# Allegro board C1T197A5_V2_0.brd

Outline 36.2 x 146 mm; copper layers: TOP, KEY, BOTTOM. Coordinates in mm from the lower left corner of the outline.
Outline path: circle c8.8,80.1 r1.2 ; circle c8.86,139.5 r0.85 ; circle c11.75,43.55 r1.2 ; circle c11.75,19.35 r1.2 ; rectangle 15.9,132.2 20.4,134.2 ; circle c18.1,128 r1.2 ; circle c24.45,43.55 r1.2 ; circle c24.45,19.35 r1.2 ; circle c27.4,80.1 r1.2 ; circle c34.26,139.5 r0.85 ; 0,144 0,4 arc(1.17,1.17) 4,0 32.2,0 arc(35.03,1.17) 36.2,4 36.2,144 arc(35.61,145.41) 34.2,146 26.2,146 arc(25.49,145.71) 25.2,145 25.2,143.8 arc(24.91,143.09) 24.2,142.8 12,142.8 arc(11.29,143.09) 11,143.8 11,145 arc(10.71,145.71) 10,146 2,146 arc(0.59,145.41) 0,144

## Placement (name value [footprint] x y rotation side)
BT2  3V_2xAAA  [BAT_2DIP]  18.1 4.11 0 bottom
C1  NC  [0402]  21.17 115.84 90 bottom
C2  NC  [0402]  23.94 115.83 90 bottom
C3  NC  [0402]  26.76 115.84 90 bottom
C4  220pF  [0402]  22.55 116.33 0 bottom
C5  0.1uF  [0402]  21.83 113.92 90 bottom
C6  2.2uF  [0402]  22.71 113.92 90 bottom
C7  1uF  [0402]  22.19 117.27 0 bottom
C8  NC  [0402]  29.55 115.84 270 bottom
C9  1uF  [0402]  14.74 122.87 270 bottom
C10  1uF  [0402]  11.29 118.98 270 bottom
C12  1uF  [0402]  11.12 111.75 90 bottom
C13  NC  [0402]  21.62 122.84 270 bottom
C14  NC  [0402]  15.79 123.38 90 bottom
C15  1uF  [0402]  10.22 111.75 90 bottom
C16  1uF  [0402]  10.11 115.83 0 bottom
C17  0.1uF  [0402]  10.11 116.68 0 bottom
C18  1uF  [0402]  10.11 117.53 0 bottom
C19  NC  [0402]  12.86 124.7 0 bottom
C20  NC  [0402]  12.7 129.33 270 bottom
C22  22nF  [0402]  7.65 128.53 180 bottom
C25  1uF  [0603C]  10.73 130.58 90 bottom
C26  10uF  [0603C]  12.52 71.93 0 bottom
C31  10uF  [0603C]  11.47 138.52 270 bottom
C33  0.1uF  [0603C]  15.42 130.26 0 bottom
CD2  220uF/10V  [CD2P0_4P0B1]  12.77 67.59 0 bottom
D1  Red_LED  [1206-LED]  17.04 133.22 90 bottom
D2  Red_LED  [1206-LED]  19.29 133.22 90 bottom
D3  LED  [LED_SMD_2P54MM_2PIN]  18.45 138.15 180 bottom
L1  0R  [0402]  25.34 116.33 0 bottom
L3  4.7uH  [0805L]  7.82 113.47 0 bottom
Q2  C1815  [SOT-23]  8.42 135.62 90 bottom
R1  1K  [0402]  21.73 130.86 180 bottom
R2  1K  [0402]  21.72 131.67 180 bottom
R3  NC  [0402]  14.15 125.86 90 bottom
R4  0R  [0402]  9.65 128.5 0 bottom
R6  0R  [0402]  28.15 116.35 0 bottom
R7  680  [0603R]  24.85 122.55 90 bottom
R10  1  [0402]  13.03 138.19 90 bottom
R11  NC  [0402]  7.87 131.17 180 bottom
R13  1K  [0402]  6.27 131.68 90 bottom
R48  0  [1206R]  7.6 110.21 315 bottom
R49  0  [1206R]  6.28 122.27 225 bottom
R50  0  [1206R]  6 117.75 135 bottom
SW1  SW2PIN  [KEY1]  13.45 73.6 180 top
SW2  SW2PIN  [KEY1]  30.8 133.5 180 top
SW3  SW2PIN  [KEY1]  5.4 133.5 180 top
SW4  SW2PIN  [KEY1]  22.75 73.6 180 top
SW5  SW2PIN  [KEY1]  4.15 73.6 180 top
SW8  SW2PIN  [KEY1]  18.1 62 180 top
SW9  SW2PIN  [KEY1]  32.05 122.1 180 top
SW10  SW2PIN  [KEY1]  4.15 122.1 0 top
SW11  SW2PIN  [KEY1]  30.6 62 180 top
SW12  SW2PIN  [KEY1]  5.6 62 180 top
SW15  SW2PIN  [KEY1]  18.1 49.6 180 top
SW16  SW2PIN  [KEY1]  31.6 98 180 top
SW17  SW2PIN  [KEY1]  13.45 122.1 0 top
SW18  SW2PIN  [KEY1]  30.8 49.6 270 top
SW19  SW2PIN  [KEY1]  5.4 49.6 90 top
SW22  SW2PIN  [KEY1]  18.1 37.5 180 top
SW23  SW2PIN  [KEY1]  18.1 98 270 top
SW24  SW2PIN  [KEY1]  22.75 122.1 0 top
SW25  SW2PIN  [KEY1]  30.8 37.5 270 top
SW26  SW2PIN  [KEY1]  5.4 37.5 90 top
SW29  SW2PIN  [KEY1]  18.1 25.4 180 top
SW30  SW2PIN  [KEY1]  18.1 84.5 270 top
SW31  SW2PIN  [KEY1]  18.1 111.5 0 top
SW32  SW2PIN  [KEY1]  30.8 25.4 180 top
SW33  SW2PIN  [KEY1]  32.05 73.6 180 top
SW34  SW2PIN  [KEY1]  18.1 13.3 180 top
SW35  SW2PIN  [KEY1]  30.8 13.3 270 top
SW36  SW2PIN  [KEY1]  4.6 98 180 top
SW37  SW2PIN  [KEY1]  5.4 25.4 180 top
SW38  SW2PIN  [KEY1]  5.4 13.3 90 top
TP2  SWS  [TP100]  12.57 100.75 180 bottom
TP3  VDD  [TP100]  5.31 8.31 180 bottom
TP4  GND  [TP100]  31.03 8.51 180 bottom
TP5  TX  [TP100]  10.87 102.89 180 bottom
TP8  RX  [TP100]  12.8 102.85 180 bottom
U1  TLSR8278F1KET48  [QFN_7X7_48PIN_0P5_4P20X4P20]  16.12 115.08 90 bottom
U4  -  [SPU0410LR5H-QB]  13.29 133.86 0 bottom
Y1  24MHz-12pF-+/-20ppm  [OSCCC250X320X110]  18.75 122.91 270 bottom
Y2  32.768KHz - 9pf - +/-20ppm  [OSC_2X6_SMT]  8.8 126.85 0 bottom

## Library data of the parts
BT2 = BATTERY_2xAAA_3V
C1 = C1608_NC_8
C2 = C1608_NC_2
C3 = C1608_NC_6
C4 = C1608_NC_5
C5-C7 C9 C10 = C1005X5R1C104K
C8 = C1608_NC_7
C12 C15-C18 C25 = C1005X5R1C105K
C13 C14 = C1005_NC
C19 = C1608_NC_3
C20 = C1608_NC_4
C22 = C1005C0G1H223J
C26 = C1608X5R0J106M_0
C31 = C1608X5R1A226M
C33 = C1608X5R0J106M
CD2 = CD_220uF_16V
D1 D2 = 0603D_Red: Tolerance: RichardLC; User Part Number: pn
D3 = Led_Th_3mm_1: Tolerance: RichardLC; User Part Number: partnum
L1 = MLK1608_0
L3 = IND_0
Q2 = NPN_C1815
R1 R2 R4 R6 R7 = RS0402K472JT
R3 = RS0603K102JT_0
R10 = RS0805K1R0JT
R11 = RS0402_NC
R13 = RS0402K101JT
R48-R50 = RS1206_NC
SW1-SW5 SW8-SW12 SW15-SW19 SW22-SW26 SW29-SW38 = SW2PIN_0
TP2-TP5 TP8 = TestPad100
U1 = TLSR8278F1KET48_0
U4 = MULPS4CX-RM5_1
Y1 = CRYSTAL4/SM_0: Tolerance: RichardLC
Y2 = OSC_2x6_2pin_16Mhz

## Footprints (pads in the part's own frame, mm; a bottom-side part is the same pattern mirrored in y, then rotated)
0402
  rect 0.5x0.5 smd: 1(-0.5,0) 2(0.5,0)
0603C
  rect 0.8x0.8 smd: 1(-0.8,0) 2(0.8,0)
0603R
  rect 0.8x0.8 smd: 1(-0.8,0) 2(0.8,0)
0805L
  rect 1x1.2 smd: 1(-1,0) 2(1,0)
1206-LED
  rect 0.85x1.7 smd: A(-1.525,0) C(1.525,0)
1206R
  rect 0.8x1.8 smd: 1(-1.55,0) 2(1.55,0)
BAT_2DIP
  oval 0x0.8 hole 0.7x3.5: 1(-12.8,0) 2(12.8,0)
CD2P0_4P0B1
  round 0.7 hole 0.7 unplated: (-1,0) (1,0)
KEY1
  rect 0.5x0.5 smd: 1(0,0) 2(0,2.5)
LED_SMD_2P54MM_2PIN
  oval 2x4 smd: A(1.27,0) C(-1.27,0)
OSC_2X6_SMT
  oval 1.4x1.1 smd: 1(4,0.76) 2(4,-0.76)
OSCCC250X320X110
  rect 1.3x1.4 smd: 1(-0.965,1.265) 2(-0.965,-1.265) 3(0.965,-1.265) 4(0.965,1.265)
QFN_7X7_48PIN_0P5_4P20X4P20
  oval 0.6x0.26 smd: 1(-3.35,2.75) 2(-3.35,2.25) 3(-3.35,1.75) 4(-3.35,1.25) 5(-3.35,0.75) 6(-3.35,0.25) 7(-3.35,-0.25) 8(-3.35,-0.75) 9(-3.35,-1.25) 10(-3.35,-1.75) 11(-3.35,-2.25) 12(-3.35,-2.75) 25(3.35,-2.75) 26(3.35,-2.25) 27(3.35,-1.75) 28(3.35,-1.25) 29(3.35,-0.75) 30(3.35,-0.25) 31(3.35,0.25) 32(3.35,0.75) 33(3.35,1.25) 34(3.35,1.75) 35(3.35,2.25) 36(3.35,2.75)
  oval 0.26x0.6 smd: 13(-2.75,-3.35) 14(-2.25,-3.35) 15(-1.75,-3.35) 16(-1.25,-3.35) 17(-0.75,-3.35) 18(-0.25,-3.35) 19(0.25,-3.35) 20(0.75,-3.35) 21(1.25,-3.35) 22(1.75,-3.35) 23(2.25,-3.35) 24(2.75,-3.35) 37(2.75,3.35) 38(2.25,3.35) 39(1.75,3.35) 40(1.25,3.35) 41(0.75,3.35) 42(0.25,3.35) 43(-0.25,3.35) 44(-0.75,3.35) 45(-1.25,3.35) 46(-1.75,3.35) 47(-2.25,3.35) 48(-2.75,3.35)
  rect 4.2x4.2 smd: 49(0,0)
SOT-23
  rect 0.75x1.2 smd: 1(-1.016,-1.092) 2(1.016,-1.092) 3(0,1.092)
SPU0410LR5H-QB
  round 0.85 hole 0.85 unplated: (0,0)
  round 0.723 smd: 1(-0.966,2.103) 4(0.966,2.103)
  round 0.562 smd: 2(-1.015,-0.634) 3(1.016,-0.634)
  round 0.612 smd: 5(0,2.103)
TP100
  round 1 smd: 1(0,0)

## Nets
1V4: C5.2 C6.2 C16.2 C17.2 U1.19(VDD1V2) U1.20(AVDD1V2#20) U1.41(AVDD1V2#41)
GND: BT2.2(-) C1.1 C2.1 C3.1 C5.1 C6.1 C7.2 C8.2 C9.1 C10.2 C12.1 C13.1 C14.1 C15.1 C16.1 C17.1 C18.1 C19.1 C20.1 C22.2 C26.2 C31.2 C33.2 D1.C(CATHODE) D2.C(CATHODE) Q2.2(E) R11.1 R48.1 R48.2 R49.1 R49.2 R50.1 R50.2 TP4.1(TP) U1.7(DM/A[5]) U1.8(DP(SWS)/A[6]) U1.14(DVSS) U1.22(SDMP0/P4/CMP_D/B[4]) U1.23(SDMN0/P5/CMP_DF/B[5]) U1.24(SDMP1/DI/SDA/URTS/B[6]) U1.28(SDA/P4N/URTS/MDEC/C[0]) U1.42(CYC2LNA/CMP_D/7816TRX/UTX/MDEC/) U1.43(CYC2PA/CMP_DF/UCTS/D[1]) U1.49(GND) U4.2(GND#2) U4.3(GND#3) U4.5(GND#5) Y1.2 Y1.4
TL_32KI_C3: C20.2 R3.2 U1.31(P1/URX/SCK/32KIN/C[3]) Y2.2
TL_32KO_C2: C19.2 R3.1 U1.30(P0/7816TRX/UTX/SDA/32KO/C[2]) Y2.1
TL_AMICBIAS: R7.1 U1.35(P2/UCTS/P0/C[4])
TL_AMICSP: C22.1 R4.1 U1.29(SCK/P1N/P0/AUDIO_IN/C[1])
TL_ANT: C1.2 C4.1 U1.40(ANT)
TL_B0: TP8.1(TP) U1.10(P3/URX/ATSEL1/MDEC/B[0])
TL_B1: TP5.1(TP) U1.11(P4/UTX/ATSEL2/B[1])
TL_COL0: SW1.1 SW2.1 SW3.1 SW4.1 SW5.1 U1.36(P3N/URX/ATSEL0/C[5])
TL_COL1: SW8.1 SW9.1 SW10.1 SW11.1 SW12.1 U1.2(DMIC_DI/P0N/URX/MDEC/A[0])
TL_COL2: SW15.1 SW16.1 SW17.1 SW18.1 SW19.1 U1.12(P5/UCTS/CYC2LNA/B[2])
TL_COL3: SW22.1 SW23.1 SW24.1 SW25.1 SW26.1 U1.6(CK/SCL/URTS/P2/A[4])
TL_COL4: SW29.1 SW30.1 SW31.1 SW32.1 SW37.1 U1.5(DI/SDA/UCTS/P1/A[3])
TL_COL5: SW33.1 SW34.1 SW35.1 SW36.1 SW38.1 U1.45(P1N/I2SSDI/7816TRX/UTX/D[3])
TL_IROUT: R11.2 R13.1 U1.13(P0N/URTS/CYC2PA/B[3])
TL_LED1: R1.1 U1.37(CYC2LNA/ATSEL1/P4N/C[6])
TL_LED2: R2.1 U1.38(CYC2PA/ATSEL2/P5N/C[7])
TL_ROW0: SW1.2 SW8.2 SW15.2 SW22.2 SW29.2 SW34.2 U1.47(P0/CMP_D/P0N/D[5])
TL_ROW1: SW2.2 SW9.2 SW16.2 SW23.2 SW30.2 SW33.2 U1.44(CN/I2SLR/P3/D[2])
TL_ROW2: SW3.2 SW10.2 SW17.2 SW24.2 SW31.2 SW36.2 U1.46(SWM/I2SSDO/P2N/D[4])
TL_ROW3: SW4.2 SW11.2 SW18.2 SW25.2 SW32.2 SW35.2 U1.48(CN/URX/ATSEL0/D[6])
TL_ROW4: SW5.2 SW12.2 SW19.2 SW26.2 SW37.2 SW38.2 U1.1(CK/SCL/I2SBCK/7816TRX/UTX/D[7])
TL_RST: C7.1 U1.39(RESETB)
TL_SWS: TP2.1(TP) U1.9(SWS/URTS/A[7])
TL_VDD: BT2.1(+) C10.1 C15.2 C26.1 C31.1 R10.2 TP3.1(TP) U1.16(VDD_IO) U1.27(VDD3)
TL_XC1: C13.2 U1.34(XC1) Y1.3
TL_XC2: C14.2 U1.33(XC2) Y1.1
N21000893: D2.A(ANODE) R2.2
N21007782: D1.A(ANODE) R1.2
N21115397: C8.1 R6.2
N21115407: C2.2 C4.2 L1.1
N21115415: C3.2 L1.2 R6.1
N21116055: C12.2 U1.15(VDD1V)
N21116211: L3.2 U1.17(VDCDC_SW)
N21116214: L3.1 U1.18(VDCDC)
N21116508: C18.2 U1.21(VDD_F)
N21117063: C9.2 U1.32(VMID)
N21140224: C25.2 U4.1(OUTPUT)
N21140411: C33.1 R7.2 U4.4(VDD)
N21149600: C25.1 R4.2
N21152572: D3.A(ANODE) R10.1
N21152638: Q2.1(B) R13.2
N21152650: D3.C(CATHODE) Q2.3(C)

Pads without a net: U1 3 4 25 26

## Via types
v1: diameter 1.5, hole 0.7, TOP to BOTTOM, 25 vias
v2: diameter 1.5, hole 0.001, TOP to BOTTOM, 27 vias

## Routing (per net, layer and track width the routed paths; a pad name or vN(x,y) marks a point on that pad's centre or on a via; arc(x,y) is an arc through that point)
1V4: length 19.3
  BOTTOM w0.3: C5.2 21.73,114.52 21.56,114.52 21.55,114.53 20.98,114.53 20.78,114.74 20.57,114.94 20.57,115.13 19.87,115.83 U1.41 18.72,115.83 18.57,115.98 18.57,117.32 18.36,117.53 13.87,117.53 13.67,117.32 13.67,116.12 13.37,115.83 U1.20 11.86,115.83 11.01,116.68 C17.2 C16.2 11.11,115.33 U1.19
  BOTTOM w0.5: C5.2 21.84,114.42 C6.2
GND: length 428.2
  BOTTOM w0.2: C12.1 11.07,111.3 ; 22,113.1 21.73,113.1 20.97,113.87 ; U1.23 12.17,117.33 12,117.5 ; 12,112.1 11.15,111.25 ; U1.28 14.87,119.23 14.04,120.06 12.64,120.06 12.4,120.3 12.1,120.3 ; 30.9,10.01 31.03,9.88 ; U1.22 12.24,116.83 12,117.07 ; 20.8,114.08 21.04,114.08 21.19,113.93 21.13,113.87 20.97,113.87 ; 20.8,114.08 20.76,114.12 20.72,114.12 20.01,114.83 20.01,115.06 19.74,115.33 U1.42 16.37,115.33 U1.49 ; 20.8,114.08 20.8,114.04 20.97,113.87 ; 21.22,115.34 C1.1 21.07,115.34 ; 11.9,117.9 11.97,117.83 U1.24 ; 15.37,114.33 U1.8 15.37,108.78 ; 15.87,114.83 U1.7 15.87,109.41
  BOTTOM w0.3: 12.12,112.51 12.12,112.53 12.42,112.83 ; 23.92,122.55 25.72,122.55 25.81,122.64 ; 16.37,114.83 16.12,114.83 U1.49 ; 16.37,114.83 U1.49 ; 16.37,114.83 U1.43 20.01,114.83 ; 19.3,119.1 19.5,119.3 ; 19.4,119.1 22.84,119.1 23.24,119.5 23.8,119.5 ; 12.42,112.83 U1.14 13.87,112.83 U1.49 ; 12.42,112.83 12.03,112.83 12,112.8 12,112.39 11.87,112.27
  BOTTOM w0.4: 24,119.3 19.6,119.3 19.4,119.1 19.3,119.1 ; C14.1 15.79,121.56 16.95,120.4 16.95,120.43 17.49,120.97 Y1.4
  BOTTOM w0.5: 21.19,113.93 21.7,113.42 C5.1 ; 21.6,124.6 21.2,125 16.2,125 16.1,124.9 15.4,124.9 14.74,124.24 C9.1 14.81,123.37 15.11,123.07 15.18,123.07 15.37,122.88 C14.1 16.73,121.94 Y1.4 ; 21.6,124.6 22.35,123.85 22.35,121.55 ; 21.6,124.6 21.6,123.36 C13.1 ; C7.2 27.16,117.27 27.59,117.7 ; 10.4,118.51 10.2,118.71 10,118.51 ; 10.4,118.51 10.86,118.51 11.06,118.71 C10.2 ; 10.4,118.51 10,118.51 ; 23.83,122.64 23.49,122.3 23.1,122.3 22.35,121.55 ; 23.83,122.64 22.84,123.63 22.84,124.17 21.81,125.19 21.59,125.19 21.56,125.22 16.7,125.22 15.94,125.98 ; 23.83,122.64 23.92,122.55 ; 22.35,121.55 21.7,120.9 21.7,120.8 21.1,120.8 ; C12.1 11.45,111.25 12,111.8 12,112.39 ; 18.53,119.87 18.7,120.05 18.71,120.05 19.46,120.8 21.1,120.8 ; 11.49,124.7 11.01,124.7 11,124.71 ; 11.49,124.7 11,124.21 ; 11.49,124.7 C19.1 ; 15.8,130.01 15.47,130.34 15.47,130.85 15.4,130.91 15.4,131.08 ; C33.2 15.4,131.08 ; 15.4,131.08 15.4,132.51 ; 12,122.61 12,122.31 13.3,121.01 ; 21.7,121.4 21.1,120.8 ; 11.9,120.33 12.08,120.33 12.23,120.18 12.3,120.18 ; 8.37,131.95 8.2,132.12 8.2,133.86 8.38,134.04 8.38,135.17 8.2,135.34 8.2,136.64 ; 10,118.51 10,118.06 9.91,117.97 9.91,117.83 C18.1 ; 10,118.51 9.92,118.51 9.71,118.31 9,118.31 8.7,118.01
  BOTTOM w0.8: C33.2 16.27,130.21 17.4,130.21 17.41,130.2 18.32,130.2 18.74,130.12 19.14,129.95 19.2,129.91 19.9,129.91 20,130.01 26.4,123.61 26.4,121.21 24.69,119.5 23.8,119.5 ; 15.4,124.9 15.94,125.44 15.94,125.98 15.18,126.75 15.18,127.13 14,128.31 14,129.01 13.4,129.61 13.4,131.25 13.29,131.36 ; 9.38,109.8 10.83,111.25 C12.1 ; U4.5 13.29,131.75 13.29,131.36 ; 13.29,133.86 12.48,133.06 9.48,133.06 8.37,131.95 R11.1 8.37,130.39 7.15,129.18 C22.2 7.15,127.96 6.37,127.18 6.37,124.37 R49.1 8.87,123.37 10.63,121.61 10.63,121.6 11.9,120.33 ; 13.29,131.36 13.28,131.36 12.72,130.8 12.69,130.8 11.9,130.01 11.9,129.38 11.85,129.33 11.85,128.76 11,127.91 11,123.61 12,122.61 ; C31.2 11.47,136.78 11.33,136.64 Q2.2
  BOTTOM w1: 29.6,119.71 29.6,128.11 22.96,134.75 D2.C ; 29.6,119.71 29.6,117.61 27.68,117.61 27.59,117.7 29.6,119.71
  BOTTOM w1.2: R50.1 6.99,116.65 5.3,114.96 5.3,112.51 6.5,111.3 ; Q2.2 6.73,136.64 6.2,136.11 6.1,136.11 4.04,134.05 4.04,122.32 R49.2 5.19,119.12 R50.2
  BOTTOM w1.5: 13.47,71.78 13.47,73.36 13.48,73.37 13.48,74.62 13.47,74.64 13.47,75.44 11.7,77.21 11.7,93.81 11.2,94.31 ; 13.47,71.78 13.47,67.89 ; 13.47,71.78 C26.2 ; 13.47,67.89 13.77,67.59 13.77,67.54 ; 13.47,67.89 13.47,67.84 13.77,67.54 ; 9.38,110.01 9.38,109.8 R48.2 7.4,107.82 7.4,98.11 11.2,94.31 ; 11.2,94.31 16,99.11 16,109.28 ; 13.77,67.54 18.3,63.01 29.6,63.01 ; 30.9,8.64 TP4.1
  BOTTOM w1.8: 27.2,109.11 28.8,107.51 28.8,105.17 29.26,104.7 29.26,94.15 30.33,93.08 30.33,70 28.6,68.26 28.6,64.21 29.05,63.76 29.05,63.66
  BOTTOM w2: 30.9,61.81 30.9,52.01 31.96,50.95 31.96,19.77 30.9,18.71 BT2.2 ; 30.9,61.81 29.05,63.66 29.05,63.56 30.8,61.81 30.9,61.81 ; 31.03,9.88 TP4.1
TL_32KI_C3: length 13
  BOTTOM w0.2: U1.31 16.37,119.43 16.27,119.53 15.25,120.54 14.5,121.3 13.5,122.3 13.5,123.79 14.7,124.99 14.7,125.81 R3.2 13.5,127.01 13.5,127.06 12.95,127.61 Y2.2 12.7,127.71 C20.2
TL_32KO_C2: length 10.2
  BOTTOM w0.2: 13.36,125.18 13.96,125.18 R3.1 ; 13.36,125.18 C19.2 12.87,124.21 12.87,122.36 14.33,120.9 14.85,120.38 15.87,119.36 U1.30 ; 13.36,125.18 13.36,125.53 Y2.1
TL_AMICBIAS: length 8.2
  BOTTOM w0.2: U1.35 18.37,118.93 18.93,119.5 19.24,119.8 22.9,119.8 23.05,119.95 R7.1
TL_AMICSP: length 14.4
  BOTTOM w0.2: C22.1 8.18,128.5 R4.1 9.15,124.25 12.94,120.46 14.2,120.46 15.37,119.3 U1.29
TL_ANT: length 2.6
  BOTTOM w0.3: U1.40 19.48,116.34 20.24,116.34
  BOTTOM w0.5: 21.06,116.33 21.07,116.34 ; 21.07,116.34 C1.2 21.99,116.34 C4.1 ; 21.07,116.34 20.24,116.34
TL_B0: length 9.5
  BOTTOM w0.2: U1.10 14.37,104.41 TP8.1
TL_B1: length 10.1
  BOTTOM w0.2: TP5.1 11.39,103.4 11.49,103.4 13.87,105.78 13.87,107.56 13.87,107.56 U1.11
TL_COL0: length 160.9
  TOP w0.2: v2(2.9,78.15) 4.15,76.9 SW5.1 ; SW1.1 13.45,74.08 13.4,74.13 v2(13.4,78.23) ; 28.6,137.6 29.7,137.6 30.8,136.5 SW2.1 ; 28.6,137.6 6.22,137.6 5.4,136.78 SW3.1 ; 28.6,137.6 25.4,134.4 25.4,129.03 25.39,129.02 v1(25.39,128.04) 26.37,128.04 27.17,127.24 27.17,120.57 25.43,118.83 25.43,106.23 24.23,105.03 22.85,105.03 21.7,103.89 21.7,97.07 22.82,95.95 23.25,95.95 27.85,91.35 27.85,90 27.87,89.98 27.87,84.37 28.63,83.6 v2(28.63,82.62) ; v2(23.96,78.14) 22.75,76.93 SW4.1
  KEY w1.5: v2(28.63,82.62) 28.61,82.65 25.5,82.65 23.96,81.11 v2(23.96,78.14) 19.59,78.14 18.95,77.5 15.76,77.5 15.03,78.23 v2(13.4,78.23) 11.77,78.23 11.04,77.5 5.61,77.5 5.35,77.6 5,77.67 4.53,78.15 v2(2.9,78.15)
  BOTTOM w0.2: v1(25.39,128.04) 27.16,128.04 27.86,127.34 27.86,120.57 25.94,118.65 19.85,118.65 19.63,118.43 U1.36
TL_COL1: length 188
  TOP w0.2: v2(18.1,66.55) 18.9,67.35 18.9,76.51 20.63,78.24 20.63,78.24 21.34,78.95 24.19,81.8 24.19,84.52 24.21,84.54 24.21,85.91 22.67,87.44 v1(21.95,87.44) 21.95,89.25 24.4,91.7 24.4,91.79 24.41,91.79 24.41,93.16 23.27,94.3 21.45,94.3 v2(20.75,93.6) ; 4.15,117.35 SW10.1 ; 4.15,117.35 7.03,120.23 7.03,121.49 7.82,122.28 v2(7.82,125.03) ; 4.15,117.35 4.15,108.6 10.63,102.12 10.63,98.15 14.2,94.58 v2(14.2,93.6) ; v2(32.08,127.2) 32.08,122.61 32.05,122.58 SW9.1
  TOP w0.5: v2(30.6,66.55) SW11.1 ; SW8.1 v2(18.1,66.55) ; SW12.1 v2(5.6,66.55)
  KEY w0.5: v2(5.6,66.55) 5.6,62.56
  KEY w1.5: v2(7.82,125.03) 7.82,127.26 11.11,130.56 27.1,130.56 30.46,127.2 v2(32.08,127.2) ; v2(30.6,66.55) v2(18.1,66.55) 16.57,66.55 15.56,65.53 8.24,65.53 7.23,66.55 v2(5.6,66.55) ; v2(14.2,93.6) 19.12,93.6 v2(20.75,93.6)
  BOTTOM w0.2: U1.2 18.37,110.43 19.9,108.9 19.9,108.22 20.53,107.59 20.53,92.34 21.3,91.57 21.3,88.1 v1(21.95,87.44)
TL_COL2: length 144.2
  TOP w0.2: 31.6,101.3 31.8,101.5 35.34,101.5 35.68,101.16 35.68,93.54 35.7,93.52 35.7,60.4 v1(33.7,58.4) ; 31.6,101.3 SW16.1 ; 31.6,101.3 30.26,101.3 v2(27.56,104) ; SW18.1 v2(26.22,49.6) 26.22,50.58 29.83,54.19 v1(33.7,54.19) ; SW19.1 v2(10,49.6) ; v2(12,105.26) 12.22,105.48 v1(12.22,106.87) 13.33,107.98 13.33,109.89 11.8,111.42 11.8,117.5 13.45,119.15 SW17.1
  TOP w0.5: SW15.1 v2(18.1,54.1)
  KEY w1.5: v2(10,49.6) 14.5,54.1 v2(18.1,54.1) 21.73,54.1 25.07,50.76 25.07,50.75 v2(26.22,49.6) ; v2(27.56,104) 26.96,104.6 15.21,104.6 14.68,105.13 v2(12,105.26)
  BOTTOM w0.2: U1.12 13.37,108.02 v1(12.22,106.87) ; v1(33.7,54.19) v1(33.7,58.4)
TL_COL3: length 155.5
  TOP w0.2: SW24.1 22.75,118.6 25.03,116.32 25.03,106.4 24.06,105.43 22.68,105.43 21.95,104.7 18.8,104.7 14.9,100.8 14.9,98.4 ; SW23.1 15.3,98 14.9,98.4 ; 14.9,98.4 14.9,96.1 17.4,93.6 v1(17.4,90.9) ; v2(9.86,37.5) SW26.1 ; SW25.1 v2(26.27,37.5) ; v1(20.76,80.7) 20.76,79.56 18.3,77.1 18.3,69.17 14.38,65.25 14.38,47.02 18.01,43.39 v2(18.1,42.42) SW22.1
  KEY w0.2: 18.1,98.1 18.2,98
  KEY w1.5: v2(9.86,37.5) 14.78,42.42 v2(18.1,42.42) 21.31,42.42 25.08,38.65 25.12,38.65 v2(26.27,37.5)
  BOTTOM w0.2: U1.6 16.37,111.13 17.21,110.29 17.21,106.24 20.13,103.32 20.13,94.61 17.4,91.88 v1(17.4,90.9) 17.4,89.92 18.7,88.62 18.7,85.4 20.76,83.34 v1(20.76,80.7)
TL_COL4: length 144.7
  TOP w0.2: v1(15,90.8) 15.69,91.49 15.69,91.52 15.85,91.68 15.85,94.28 14.4,95.73 14.4,101.45 18.88,105.93 v1(18.88,106.91) 18.1,107.69 SW31.1 ; v1(18,79.8) 17.7,79.8 ; 17.7,79.8 16.36,79.8 14.14,82.02 14.14,84 14.64,84.5 SW30.1 ; 17.7,79.8 17.7,69.14 13.8,65.24 13.8,34.78 v2(18.1,30.48) SW29.1 ; v2(30.16,30.48) 30.85,29.79 30.85,25.45 SW32.1 ; v2(7.05,30.48) 5.4,28.83 SW37.1
  KEY w1.5: v2(7.05,30.48) v2(18.1,30.48) v2(30.16,30.48)
  BOTTOM w0.2: v1(15,90.8) 15.69,90.11 15.72,90.11 17.31,88.52 17.31,80.49 v1(18,79.8) ; U1.5 16.87,111.2 18.88,109.19 v1(18.88,106.91)
TL_COL5: length 185.1
  TOP w0.2: SW34.1 v2(18.1,17.9) ; SW36.1 4.6,101.5 5.3,102.2 6.8,102.2 v2(8.98,100.02) ; v1(33.75,17.14) 29.34,17.14 26.4,14.2 26.4,13.5 26.2,13.3 ; 32.05,78.37 SW33.1 ; 32.05,78.37 v1(33.65,78.37) ; 32.05,78.37 32.05,81.55 28.4,85.2 28.4,91.6 23.5,96.5 v1(23.5,97.6) 23.5,100.87 23.51,100.88 v2(23.51,101.86) ; 26.2,13.3 SW35.1 ; 26.2,13.3 v2(26.19,13.29) ; v2(10.05,13.3) SW38.1
  KEY w1.5: v2(8.98,100.02) 12.2,100.02 13.59,101.41 13.61,101.41 14.6,102.4 21.39,102.4 21.88,101.91 22.53,101.91 22.58,101.86 v2(23.51,101.86) ; v2(10.05,13.3) 11.2,14.45 11.27,14.45 14.72,17.9 v2(18.1,17.9) 21.64,17.9 25.04,14.5 25.04,14.44 v2(26.19,13.29)
  BOTTOM w0.2: U1.45 19.88,113.83 20.9,112.8 20.9,111.03 22.33,109.6 22.34,109.6 23.2,108.73 24.06,108.73 25.03,107.77 25.03,103.04 22.4,100.41 22.4,98.7 v1(23.5,97.6) ; v1(33.75,17.14) 35.4,18.79 35.4,76.62 v1(33.65,78.37)
TL_IROUT: length 29.5
  TOP w0.2: v1(8.68,120.81) 8.68,113.42 11.68,110.42 v1(11.68,109.21)
  BOTTOM w0.2: U1.13 12.77,110.3 v1(11.68,109.21) ; R11.2 6.76,131.17 6.75,131.18 R13.1 5.51,130.42 5.51,123.87 v1(8.68,120.81)
TL_LED1: length 24.5
  BOTTOM w0.2: R1.1 22.71,130.86 22.72,130.88 24.89,130.88 28.26,127.51 28.26,120.24 26.27,118.25 20.55,118.25 20.13,117.83 U1.37
TL_LED2: length 26.1
  BOTTOM w0.2: U1.38 20.23,117.33 20.75,117.85 26.44,117.85 28.66,120.07 28.66,123.75 28.66,127.73 24.71,131.68 22.7,131.68 22.7,131.67 R2.1
TL_ROW0: length 154.8
  TOP w0.2: 21.78,55.82 SW8.2 18.1,59.02 17.45,58.37 17.42,58.37 v1(16.73,57.68) ; 21.78,55.82 21.78,43.43 ; 21.78,55.82 21.78,66.72 19.45,69.05 19.45,76.4 21.69,78.64 21.69,78.65 24.59,81.55 24.59,81.95 24.59,83.84 24.64,83.89 24.64,88.25 v1(24.51,88.38) ; 21.78,43.43 21.77,43.43 SW15.2 ; 21.78,43.43 21.78,31.32 ; SW1.2 13.45,69.14 12.84,68.53 12.84,66.3 11.87,65.33 v1(11.87,61.71) ; 21.78,31.32 21.78,19.22 ; 21.78,31.32 SW22.2 ; 21.78,19.22 SW29.2 ; 21.78,19.22 21.78,12.19 20.39,10.8 SW34.2
  KEY w1.5: v1(16.73,57.68) 14.27,57.68 11.87,60.08 v1(11.87,61.71)
  BOTTOM w0.2: U1.47 19.75,112.83 20.1,112.47 20.1,110.7 21.23,109.57 21.23,108.59 21.73,108.09 21.73,96.46 24.88,93.31 25.59,93.31 27.3,91.6 27.3,89.5 26.18,88.38 v1(24.51,88.38)
TL_ROW1: length 146.3
  TOP w0.2: SW23.2 20.6,95.9 20.25,95.55 ; SW2.2 35.5,126.3 35.5,120.4 34.7,119.6 SW9.2 31.4,119.6 25.89,114.09 25.89,100.59 v1(25.2,99.9) 25.2,98.92 28.62,95.5 SW16.2 35.3,91.8 35.3,71.8 34.6,71.1 SW33.2 29.6,71.1 26.8,73.9 26.8,77.97 26.01,78.76 26.01,78.8 25.92,78.89 25.72,79.2 25.66,79.34 25.42,79.58 25.42,83.53 25.48,83.59 25.48,83.61 27.45,85.58 27.45,91.18 26.48,92.15 26.45,92.15 23.05,95.55 20.25,95.55 ; v1(19.65,90.23) 19.65,91.21 19.11,91.74 19.11,92.89 19.09,92.91 19.09,94.28 19.11,94.3 19.11,94.41 20.25,95.55 ; v1(22.56,85.22) 21.84,84.5 SW30.2
  BOTTOM w0.2: v1(22.56,85.22) 21.58,85.22 19.65,87.16 v1(19.65,90.23) ; v1(25.2,99.9) 25.2,100.88 25.43,101.11 25.43,107.93 24.23,109.13 23.37,109.13 22.5,110 22.5,110 21.3,111.2 21.3,112.97 19.94,114.33 U1.44
TL_ROW2: length 98.4
  TOP w0.2: v1(23.38,107.08) 22.4,108.06 22.4,112.6 22,113 ; 22,113 22,117.6 19.35,120.25 19.35,125.37 19.98,126 ; 22,113 21.5,113.5 21.5,113.5 21,114 SW31.2 ; 0.9,124.5 1,124.6 SW10.2 6.24,126.69 11.36,126.69 SW17.2 14.85,126 19.98,126 ; 0.9,124.5 0.9,96.7 2.1,95.5 SW36.2 ; 0.9,124.5 0.9,126.5 SW3.2 ; 19.98,126 21.35,126 SW24.2
  BOTTOM w0.2: U1.46 19.81,113.33 20.5,112.64 20.5,110.87 20.5,110.87 21.7,109.67 21.7,108.76 v1(23.38,107.08)
TL_ROW3: length 127.2
  TOP w0.2: SW32.2 31.21,22.49 31.51,22.49 35.4,18.6 ; SW35.2 35.4,15.4 35.4,18.6 ; SW4.2 23.23,71.1 26.4,67.93 ; v1(25.57,90.53) 26.26,89.84 26.26,84.95 25.06,83.75 25.06,83.74 24.99,83.67 24.99,81.79 24.99,79.44 25.32,79.11 25.36,79.01 25.61,78.64 25.61,78.59 26.4,77.8 26.4,67.93 ; 26.4,67.93 26.4,60.9 27.8,59.5 SW11.2 30.6,58.6 33,56.2 34.52,56.2 35.4,55.32 35.4,47.71 ; 35.4,35.4 SW25.2 ; 35.4,35.4 35.4,47.71 ; 35.4,35.4 35.4,18.6 ; 35.4,47.71 35.19,47.71 SW18.2
  BOTTOM w0.2: U1.48 19.47,110.7 20.83,109.34 20.83,108.43 21.33,107.92 21.33,96.24 24.41,93.16 24.41,91.69 v1(25.57,90.53)
TL_ROW4: length 141.5
  TOP w0.2: 1.91,55.88 1.91,68.86 ; 1.91,55.88 1.91,48.61 ; 1.91,55.88 1.98,55.88 SW12.2 ; 1.91,68.86 SW5.2 ; 1.91,68.86 0.8,69.98 0.8,79 6.96,85.16 ; 6.96,85.16 v1(6.96,93.94) ; 6.96,85.16 8.04,86.24 13.01,86.24 15.34,88.57 20.58,88.57 21.28,89.27 21.28,89.53 21.3,89.55 21.3,91.02 v1(22.76,92.48) ; 1.91,48.61 SW19.2 ; 1.91,48.61 1.91,36.51 ; 1.91,36.51 1.91,18.74 ; 1.91,36.51 SW26.2 ; 1.91,18.74 1.91,14.29 SW38.2 ; 1.91,18.74 5.4,22.23 SW37.2
  BOTTOM w0.2: U1.1 18.87,110.73 20.4,109.2 20.4,108.29 20.93,107.76 20.93,95.57 22.76,93.74 v1(22.76,92.48)
TL_RST: length 2.4
  BOTTOM w0.2: C7.1 21.58,117.27 21.54,117.23 20.73,117.23 20.39,116.89 20.01,116.89 19.95,116.83 U1.39
TL_SWS: length 11.9
  BOTTOM w0.2: U1.9 14.87,109.9 14.82,109.85 14.82,103 TP2.1
TL_VDD: length 257.2
  BOTTOM w0.2: 5.3,6.84 5.31,6.85 TP3.1
  BOTTOM w0.3: 10.54,113.6 10.76,113.83 U1.16 ; 14.01,119.31 14.06,119.31 14.37,119 U1.27
  BOTTOM w0.5: R10.2 12.4,139.32 C31.1 9.86,137.71 5.95,137.71 2.93,134.69 2.93,79.64 9.16,73.41 10.24,73.41 ; 10.54,113.6 10.22,113.17 C15.2 9.6,112.25 5.1,107.75 5.1,80 6.68,78.42 6.71,78.37 6.71,78.37 6.75,78.28 10.6,74.42 10.6,73.05 ; 10.6,73.05 10.24,73.41 ; 10.6,73.05 C26.1 ; 10.24,73.41 10.25,73.41 ; 10.24,73.41 10.1,73.55 10.1,73.66 ; 10.1,73.66 10.1,73.8 10,73.8 3.98,79.82 3.98,115.89 7.1,119.01 9.42,119.01 9.9,119.48 C10.1 11.44,119.48 11.44,119.48 13.75,119.48 13.85,119.47 14.01,119.31 ; 10.1,73.66 10.35,73.41
  BOTTOM w1: 5.3,8.29 BT2.1 ; 5.3,8.29 TP3.1 ; 5.3,8.29 5.3,61.12 11.77,67.59 11.77,70.85 11.72,70.9 C26.1
TL_XC1: length 6.3
  BOTTOM w0.2: U1.34 17.87,118.54 17.92,118.59 17.92,120.03 18.48,120.59 18.48,120.59 19.83,121.94 Y1.3
  BOTTOM w0.3: Y1.3 21.23,121.94 C13.2
TL_XC2: length 8.1
  BOTTOM w0.2: U1.33 17.37,120.05 18.31,121 18.49,121.17 18.49,122.92 17.54,123.88 Y1.1 16.56,123.88 16.56,123.88 C14.2
N21000893: length 1.9
  BOTTOM w0.2: R2.2 20.39,131.67 20.36,131.7 D2.A
N21007782: length 4.5
  BOTTOM w0.2: R1.2 20.75,130.86 20.71,130.91 18.25,130.91 17.46,131.7 D1.A
N21115397: length 27
  BOTTOM w0.5: 33,105.36 34.99,105.36 34.99,107.34 33.1,107.34 33.1,109.2 34.97,109.2 34.97,111.3 33,111.3 33,113.4 34.97,113.4 34.97,116.34 C8.1 28.66,116.34 R6.2
N21115407: length 1.8
  BOTTOM w0.5: C4.2 23.92,116.33 C2.2 24.84,116.33 L1.1
N21115415: length 1.8
  BOTTOM w0.5: L1.2 26.75,116.33 C3.2 27.64,116.34 R6.1
N21116055: length 2.4
  BOTTOM w0.3: C12.2 11.12,112.73 11.72,113.33 U1.15
N21116211: length 4.4
  BOTTOM w0.3: L3.2 8.82,113.57 9.58,114.33 U1.17
N21116214: length 6.6
  BOTTOM w0.3: L3.1 6.82,113.57 7.67,114.42 8.94,114.42 9.35,114.83 U1.18
N21116508: length 2.7
  BOTTOM w0.2: U1.21 12,116.33 10.79,117.53 C18.2
N21117063: length 4.8
  BOTTOM w0.2: C9.2 14.74,121.62 15.65,120.71 16.67,119.69 16.87,119.49 U1.32
N21140224: length 1.7
  BOTTOM w0.2: C25.2 11.11,131.76 U4.1
N21140411: length 15.6
  BOTTOM w0.2: R7.2 22.14,126.06 17.31,126.06 15.34,128.03 15.34,129.54 C33.1
  BOTTOM w0.3: C33.1 14.62,131.4 U4.4
N21149600: length 1.5
  BOTTOM w0.2: R4.2 10.65,128.98 10.73,129.06 C25.1
N21152572: length 4.3
  BOTTOM w0.5: D3.A 15.8,138.15 15.34,137.69 R10.1
N21152638: length 2.9
  BOTTOM w0.2: Q2.1 7.33,134 6.27,132.94 R13.2
N21152650: length 11.8
  BOTTOM w0.5: D3.C 19.72,137.15 18.27,135.7 10.57,135.7 10.49,135.62 Q2.3

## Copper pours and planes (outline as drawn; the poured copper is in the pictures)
GND on BOTTOM: 4.4,8.41 4.4,78.01 2.4,78.01 2.4,139.01 18.1,139.01 18.1,135.41 20.2,135.41 20.2,134.2 15.9,134.2 15.9,132.2 20,132.2 20,131.61 25.2,131.61 25.2,130.11 27.1,130.11 27.1,128.31 28.4,128.31 28.4,119.51 27.4,119.51 27.4,118.31 22,118.31 22,117.01 31.8,117.01 31.8,118.31 31,118.31 31,118.9 35.9,118.91 35.9,119.21 31.6,119.21 35.9,119.21 35.9,107.71 31.2,107.71 31.2,108.11 29.8,108.11 29.8,104.81 25.8,104.81 25.8,108.11 24.7,108.11 24.7,107.71 11.4,107.71 11.4,109.61 7.3,109.61 7.3,107.71 6.1,107.71 6.9,108.51 6.9,109.81 4.5,112.21 4.4,112.11 4.4,107.71 3.5,107.71 3.5,81.31 4.8,81.31 4.8,81.21 11.6,74.41 12.7,74.41 12.7,67.21 10.19,67.21 10.67,67.7 10.68,67.71 10.76,68.02 10.92,68.29 10.92,70.5 10.87,70.55 10.87,70.77 8.73,70.77 8.73,72.99 4.57,77.15 4.47,77.17 4.4,77.08 4.4,61.66 4.47,61.57 4.57,61.6 5.59,62.62 6.7,61.51 4.9,61.51 4.9,8.41 ; 25 cut-outs
GND on BOTTOM: 29.9,115.71 29.9,120.21 27.1,120.21 27.1,115.71
TL_VDD on BOTTOM: 9.08,74.17 9.08,71.12 12.38,71.12 12.38,74.17

Small or netless copper shapes (teardrops, artwork), in the pictures only: 60 on KEY

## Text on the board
Ref Des/Silkscreen Bottom: VDD | B1/TX | SWS | B0/RX | GND
User.Comments: AMJ-151029 | AMJ-160130 | +
Ref Des/Silkscreen Top: 2019-11-15 | C1T197A5_V2.0
COMPVAL_TYPE_TOP: FIGURE | SIZE | 0.001 | 0.7 | 0.85 | 3.5x0.7 | DRILL CHART: TOP to BOTTOM | ALL UNITS ARE IN MILLIMETERS | PLATED | NON-PLATED | QTY | 27 | 25 | 2 | 1
User.6: +
